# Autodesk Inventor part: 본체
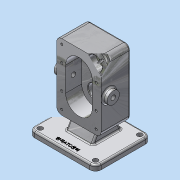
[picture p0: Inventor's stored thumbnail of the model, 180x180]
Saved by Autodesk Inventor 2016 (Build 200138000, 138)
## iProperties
Created: 2020-04
Part Number: 본체
Material: 알루미늄 6061
Document SubType Name: Modeling
Designer: Administrator
Density: 2.7 g/cm^3
Appearance: 알루미늄 - 평지
Mass: 1472.54 g
Surface Area: 818.394 cm^2
Volume: 545.387 cm^3
Author: Administrator
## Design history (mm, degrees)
sketch "스케치1"
  geometry: L1 (-60, 50)-(60, 50); L2 (60, 50)-(60, -50); L3 (60, -50)-(-60, -50); L4 (-60, -50)-(-60, 50); L5 (-60, 50)-(60, -50); L6 (60, 50)-(-60, -50); 1 further point
  constraints: 12 end point, 2 midpoint, 2 parallel, 1 horizontal, 1 perpendicular
  dimensions: "d0" = 100 distance of L3.end L1.start; "d1" = 120 distance of L2.end L3.end
extrude "돌출1" new body sketch "스케치1" distance "d2" = 10; taper "d3" = 0 deg
sketch "스케치10"
  geometry: L1 (0, 0)-(120, 0) reference; C1 r 19 at (60, -112); 1 further point
  constraints: 1 centre point
  dimensions: "d48" = 112 distance from line of L1 C1.centre; "d49" = 38 diameter of C1
extrude "돌출9" join sketch "스케치10" distance "d50" = 17; taper "d51" = 0 deg
sketch "스케치11"
  geometry: L1 (-40, 38)-(40, 38); L2 (40, 38)-(40, -82); L3 (40, -82)-(-40, -82); L4 (-40, -82)-(-40, 38); L5 (60, -112)-(-60, -112) reference; L6 (-40, -82)-(40, 38); 4 further points
  constraints: 10 end point, 3 midpoint, 2 parallel, 1 horizontal, 1 perpendicular, 1 vertical alignment
  dimensions: "d52" = 120 distance of L1.end L2.end; "d53" = 80 distance of L1.start L1.end; "d54" = 90 distance from line of L5 point (0, -22)
extrude "돌출10" join sketch "스케치11" distance "d55" = 53; taper "d56" = 0 deg
sketch "스케치12"
  geometry: L1 (-50, 0)-(50, 0) reference; L2 (-20, 150)-(-20, 30) reference; C1 r 11 at (-6, 90); 1 further point
  constraints: 1 centre point
  dimensions: "d57" = 90 distance from line of L1 C1.centre; "d58" = 22 diameter of C1; "d59" = 14 distance from line of C1.centre L2
extrude "돌출11" join sketch "스케치12" stored distance "d60" = 96; taper "d61" = 0 deg
sketch "스케치13"
  geometry: L1 (0, -44)-(0, 0); L2 (24, -44)-(24, 0); L3 (-24, 0)-(-24, -44); L4 (60, -112)-(-60, -112) reference; A1 r 24 centre (0, -44) between (-24, -44) and (24, -44); A2 r 24 centre (0, 0) between (24, 0) and (-24, 0); 3 further points
  constraints: 8 end point, 4 point on circle, 4 tangent, 2 centre point, 2 midpoint, 1 parallel, 1 vertical, 1 vertical alignment
  dimensions: "d62" = 90 distance from line of L4 point (0, -22); "d63" = 44 distance of L1.start L1.end; "d64" = 24 radius of A2
extrude "돌출12" cut sketch "스케치13" distance "d65" = 29; taper "d66" = 0 deg
sketch "스케치14"
  geometry: C1 r 12.5 at (0, 0); C2 r 12.5 at (0, -44); A1 r 24 centre (0, 0) between (24, 0) and (-24, 0) reference; A2 r 24 centre (0, -44) between (-24, -44) and (24, -44) reference; 1 further point
  constraints: 2 centre point, 2 coincident
  dimensions: "d67" = 25 diameter of C1; "d68" = 25 diameter of C2
extrude "돌출13" cut sketch "스케치14" distance "d69" = 15; taper "d70" = 0 deg
sketch "스케치15"
  geometry: C1 r 12.5 at (0, 0) reference; C2 r 8.5 at (0, 0); 1 further point
  constraints: 1 centre point, 1 coincident
  dimensions: "d71" = 17 diameter of C2
extrude "돌출14" cut sketch "스케치15" stored distance "d72" = 15; taper "d73" = 0 deg
sketch "스케치16"
  geometry: C1 r 19 at (0, 0) reference; C2 r 14 at (0, 0); 1 further point
  constraints: 1 centre point, 1 coincident
  dimensions: "d74" = 28 diameter of C2
extrude "돌출15" cut sketch "스케치16" distance "d75" = 7.3; taper "d76" = 0 deg
chamfer "모따기2" distance "d77" = 0.7; stored, may be unused: second distance "d78" = 2, angle "d79" = 30 deg
hole "구멍2" diameter "d82" = 8.376; stored, may be unused: countersink angle "d86" = 90 deg, drill point angle "d88" = 118 deg; dims "d80" = 10, "d81" = 10, "d83" = 20, "d84" = 4, "d85" = 2, "d87" = 27.3
hole "구멍3" diameter "d91" = 8.376; stored, may be unused: countersink angle "d95" = 90 deg, drill point angle "d97" = 118 deg; dims "d89" = 10, "d90" = 10, "d92" = 20, "d93" = 4, "d94" = 2, "d96" = 27.3
sketch "스케치17"
  geometry: L1 (-48, -11)-(-48, -33) reference; L2 (-48, -22)-(48, -22); L3 (48, -17.812)-(48, -26.188) reference; L4 (-40, 38)-(40, 38) reference; L5 (0, 38)-(0, -82); L6 (-40, -82)-(40, -82) reference; 2 further points
  constraints: 4 end point, 4 midpoint
  dimensions: "d98" = 31 distance from line of L5 point (-31, 29); "d99" = 51 distance from line of point (-31, 29) L2
hole "구멍4" sketch "스케치17" at (-31, 29) diameter "d100" = 4.134; stored, may be unused: countersink angle "d104" = 90 deg, drill point angle "d106" = 118 deg; dims "d101" = 10, "d102" = 4, "d103" = 2, "d105" = 12
sketch "스케치18"
  geometry: L1 (-48, -11)-(-48, -33) reference; L2 (-48, -22)-(48, -22); L3 (48, -33)-(48, -11) reference; L4 (-40, 38)-(40, 38) reference; L5 (0, 38)-(0, -82); L6 (40, -82)-(-40, -82) reference; 2 further points
  constraints: 4 end point, 4 midpoint
  dimensions: "d113" = 31 distance from line of L5 point (-31, -73); "d114" = 51 distance from line of L2 point (-31, -73)
hole "구멍5" sketch "스케치18" at (-31, -73) diameter "d115" = 4.134; stored, may be unused: countersink angle "d119" = 90 deg, drill point angle "d121" = 118 deg; dims "d116" = 10, "d117" = 4, "d118" = 2, "d120" = 12
sketch "스케치19"
  geometry: L1 (50, 10)-(-50, 10) reference; L2 (-20, 10)-(-8.453, 30); L3 (33, 30)-(-20, 30) reference; L4 (-8.453, 30)-(21.453, 30); L5 (21.453, 30)-(33, 10); L6 (33, 10)-(-20, 10); L7 (50, 0)-(50, 10) reference; 1 further point
  constraints: 8 end point, 4 point on line, 1 collinear
  dimensions: "d128" = 17 distance from line of L7 L5.end; "d129" = 53 distance of L2.start L5.end; "d130" = 60 deg angle of L2 L1; "d131" = 60 deg angle of L1 L5
extrude "돌출16" join sketch "스케치19" stored distance "d132" = 48; taper "d133" = 0 deg
fillet "모깎기1" dims "d134" = 10, "d135" = 9, "d136" = 0.5, "d137" = 3
sketch "스케치20"
  geometry: A1 r 10 centre (-50, 40) between (-50, 50) and (-60, 40) reference; A2 r 10 centre (50, 40) between (60, 40) and (50, 50) reference; A3 r 10 centre (50, -40) between (50, -50) and (60, -40) reference; A4 r 10 centre (-50, -40) between (-60, -40) and (-50, -50) reference; 5 further points
  constraints: 4 coincident
hole "구멍7" sketch "스케치20" at (-50, 40), (50, 40), (50, -40), (-50, -40) diameter "d147" = 9; stored, may be unused: countersink angle "d151" = 90 deg, drill point angle "d153" = 118 deg; dims "d148" = 10, "d149" = 4, "d150" = 2, "d152" = 12
fillet "모깎기2" dims "d154" = 3
chamfer "모따기3" distance "d155" = 1; stored, may be unused: second distance "d156" = 2, angle "d157" = 30 deg
sketch "스케치21"
  geometry: L1 (-50, -50)-(50, -50) reference; L2 (-60, 40)-(-60, -40) reference; 2 further points
  constraints: 1 other
  dimensions: "d158" = 10 distance from line of L1 point (0, -40); "d159" = 60 distance from line of L2 point (0, -40)
feature "엠보싱1" sketch "스케치21" dims "d0" = 100, "d1" = 120, "d160" = 0.5, "d161" = 0
feature "분할1"
node "솔리드1"
pattern_linear "직사각형 패턴1" dims "d109" = 62, "d112" = 29
pattern_linear "직사각형 패턴2" dims "d124" = 62, "d127" = 29
